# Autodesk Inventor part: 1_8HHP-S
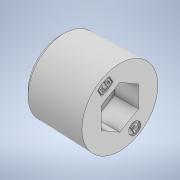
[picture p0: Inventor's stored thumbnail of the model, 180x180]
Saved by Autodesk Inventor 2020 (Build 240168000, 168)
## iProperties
Created: 2019-12
Part Number: 1_8HHP-S
Material: Generico
Description: STEP AP203
Document SubType Name: Modeling
Designer: carlo
Density: 1 g/cm^3
Appearance: Default
DataBaseUnit: MM
Title: p:/temp/worker_141/temp/exporttempdir_1132_802_j5i8P/format_0/Adapters Hexagon socket plug 1_8HHP-S.stp
Revision Number: NONE
Sending System: PARTsolutions
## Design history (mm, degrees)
feature "_Adapters Hexagon socket plug 1_8HHP-S"
node "Solido1"
